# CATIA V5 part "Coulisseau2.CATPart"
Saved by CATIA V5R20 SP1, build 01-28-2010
Part number: Coulisseau2
Bounding box of the stored display mesh (mm): x 6.28 to 26.28, y 17.651 to 24.651, z -20 to 12
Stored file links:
  F:\nsarlin\Coulisseau2.CATPart
  J:\IAO\Mecanisme_a_bielle_et_deux_coulisseaux.CATProduct
  F:\nsarlin\Coulisseau.CATPart
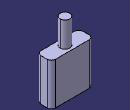
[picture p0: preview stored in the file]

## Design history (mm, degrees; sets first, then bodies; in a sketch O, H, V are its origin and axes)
Parameters
  LENGTH = 7 mm
  LENGTH = 20 mm
  LENGTH = 20 mm
External parameters (linked from other documents)
  External.Longueur_couli = 20 mm
  External.Largeur = 7 mm
  External.Epaisseur = 20 mm
  External.Longueur_Axe = 8 mm
Set1
  Plane1 "Plan_de_ref": linked copy from another document
  Point1 "Point_coulisseau2": linked copy from another document
Body1 (main body)
  Sketch1 on Plane1, origin (16.2802, 21.1511, 0), H (1, 0, 0), V (0, 1, 0)
    line L1 (-10, -1.5) -> (-10, 1.5)
    arc A1 centre (-8, 1.5) radius 2 from (-10, 1.5) to (-8, 3.5) cw
    line L2 (-8, 3.5) -> (8, 3.5)
    arc A2 centre (8, 1.5) radius 2 from (8, 3.5) to (10, 1.5) cw
    line L3 (10, 1.5) -> (10, -1.5)
    arc A3 centre (8, -1.5) radius 2 from (10, -1.5) to (8, -3.5) cw
    line L4 (8, -3.5) -> (-8, -3.5)
    arc A4 centre (-8, -1.5) radius 2 from (-8, -3.5) to (-10, -1.5) cw
    distance L4 L2 = 7 {= External.Largeur}
    radius A1 = 2
    radius A4 = 2
    radius A3 = 2
    radius A2 = 2
    distance L1 L3 = 20 {= External.Longueur_couli}
    distance L4 H = 3.5 {= External.Largeur /2}
    distance L3 V = 10 {= External.Longueur_couli /2}
    vertical: L1 V, L3 V
    tangency: A1 L1, L2 A1, A2 L2, A3 L3, L4 A3, A4 L1, A4 L4, L3 A2
  Pad1: profile Sketch1, direction (0, 0, -1), length 20 {= External.Epaisseur}
  Sketch2 on start face of Pad1, origin (16.2802, 21.1511, 0), H (1, 0, 0), V (0, 1, 0)
    circle A1 centre (0, 0) radius 2.3333
    point P1 (0, 0)
    reference projected point E1 (0, 0) from Point1
    radius A1 = 2.3333 {= External.Largeur /3}
    coincidence: P1 E1
  Pad2: profile Sketch2, direction (0, 0, 1), length 12 {= External.Epaisseur /2+2mm}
